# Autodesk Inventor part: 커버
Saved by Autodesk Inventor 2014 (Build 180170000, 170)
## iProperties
Created: 2026-04
Part Number: 커버
Material: 알루미늄 6061
Document SubType Name: Modeling
Designer: dg
Density: 2.71 g/cm^3
Appearance: 알루미늄 - 평지
Mass: 940.725 g
Surface Area: 800.62 cm^2
Volume: 347.131 cm^3
Author: jhkim
Creation Date: 2026-03-27
Sending System: Autodesk Inventor 2026
Preprocessor: ST-DEVELOPER v20.1
Author: dg
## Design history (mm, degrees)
node "커버1"
node "솔리드1"
node "기준1"
